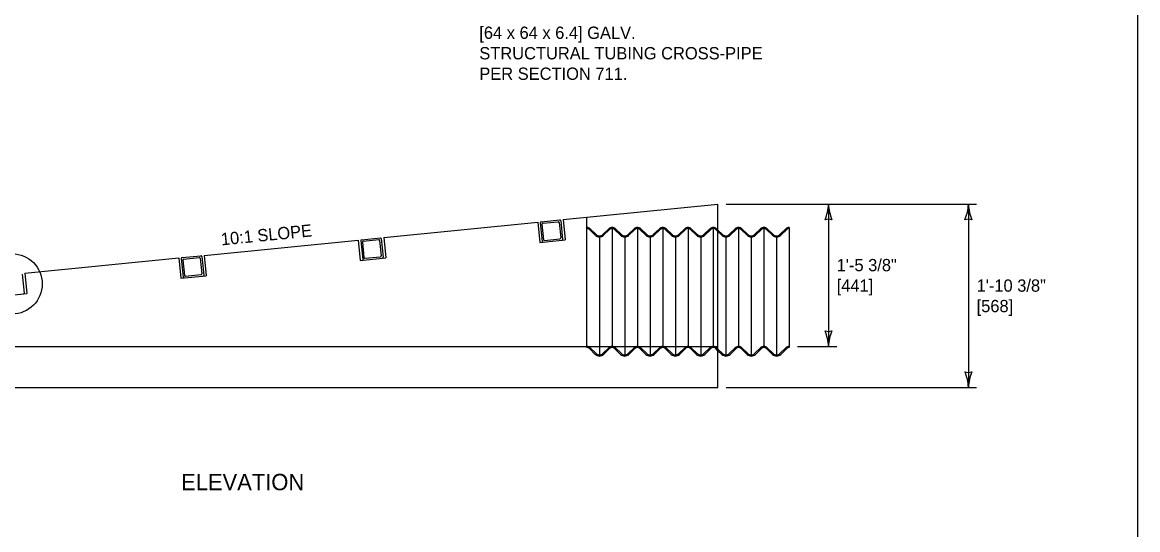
# Model space of a CAD drawing. Extents: x 49991.4 to 50021, y 49987.6 to 50011.4.
# Drawn here: x 50003.17 to 50008.61, y 50005.56 to 50008.04 of the extents above; entities that cross this region are included whole.
import ezdxf

# ---------------------------------------------------------------- set-up
doc = ezdxf.new("R2010")
doc.units = 0
for name, color, linetype in [('Level 1', 7, 'Continuous'), ('Level 2', 7, 'Continuous'), ('Level 3', 7, 'Continuous'), ('Level 4', 7, 'Continuous')]:
    doc.layers.add(name, color=color, linetype=linetype)

msp = doc.modelspace()

# ---------------------------------------------------------------- linework, layer by layer
at = {"layer": 'Level 1'}
for p, q in [((50005.8118, 50007.0772), (50006.5671, 50007.1526)), ((50006.5671, 50006.2576), (50006.5671, 50007.1526)), ((50004.9361, 50006.9899), (50005.6878, 50007.0648)), ((50005.6878, 50007.0648), (50005.6977, 50006.9653)), ((50005.7038, 50007.0664), (50005.7958, 50007.0756)), ((50005.7118, 50007.0592), (50005.7878, 50007.0668)), ((50005.8002, 50007.072), (50005.8093, 50006.9805)), ((50005.8118, 50007.0772), (50005.8217, 50006.9777)), ((50005.7002, 50007.062), (50005.7093, 50006.9705)), ((50005.7082, 50007.0548), (50005.7157, 50006.9792)), ((50005.7922, 50007.0632), (50005.7997, 50006.9876)), ((50006.5898, 50007.0046), (50006.5671, 50007.0262)), ((50006.5859, 50007.0007), (50006.5671, 50007.0185)), ((50006.6516, 50007.0326), (50006.6223, 50007.0046)), ((50006.6554, 50007.0286), (50006.6261, 50007.0007)), ((50006.6678, 50007.0391), (50006.6678, 50006.4521)), ((50006.68, 50007.0286), (50006.7093, 50007.0007)), ((50006.6839, 50007.0326), (50006.7132, 50007.0046)), ((50006.7457, 50007.0046), (50006.775, 50007.0326)), ((50006.7496, 50007.0007), (50006.7789, 50007.0286)), ((50006.7911, 50007.0391), (50006.7911, 50006.4521)), ((50006.8327, 50007.0007), (50006.8035, 50007.0286)), ((50006.8366, 50007.0046), (50006.8073, 50007.0326)), ((50006.8984, 50007.0326), (50006.8691, 50007.0046)), ((50006.9023, 50007.0286), (50006.873, 50007.0007)), ((50006.9146, 50007.0391), (50006.9146, 50006.4521)), ((50004.0605, 50006.9024), (50004.8121, 50006.9775)), ((50004.8121, 50006.9775), (50004.822, 50006.878)), ((50004.8245, 50006.9747), (50004.8337, 50006.8832)), ((50004.8281, 50006.9791), (50004.9202, 50006.9883)), ((50004.8325, 50006.9675), (50004.8401, 50006.8918)), ((50004.8361, 50006.9718), (50004.9122, 50006.9794)), ((50004.9165, 50006.9758), (50004.9241, 50006.9002)), ((50004.9245, 50006.9847), (50004.9336, 50006.8932)), ((50004.9361, 50006.9899), (50004.946, 50006.8904)), ((50005.6977, 50006.9653), (50005.8217, 50006.9777)), ((50005.7201, 50006.9756), (50005.7961, 50006.9832)), ((50006.606, 50006.998), (50006.606, 50006.4109)), ((50006.7294, 50006.998), (50006.7294, 50006.4109)), ((50006.8529, 50006.998), (50006.8529, 50006.4109)), ((50004.0605, 50006.9024), (50004.0704, 50006.803)), ((50003.1848, 50006.8151), (50003.9365, 50006.8901)), ((50003.9365, 50006.8901), (50003.9464, 50006.7906)), ((50003.9489, 50006.8873), (50003.958, 50006.7958)), ((50003.9524, 50006.8917), (50004.0445, 50006.9009)), ((50003.9569, 50006.88), (50003.9644, 50006.8044)), ((50003.9604, 50006.8844), (50004.0365, 50006.892)), ((50004.0409, 50006.8884), (50004.0484, 50006.8128)), ((50004.0489, 50006.8973), (50004.058, 50006.8057)), ((50004.822, 50006.878), (50004.946, 50006.8904)), ((50004.8444, 50006.8883), (50004.9205, 50006.8958)), ((50003.1732, 50006.81), (50003.1823, 50006.7184)), ((50003.1848, 50006.8151), (50003.1947, 50006.7156)), ((50003.9464, 50006.7906), (50004.0704, 50006.803)), ((50003.9688, 50006.8008), (50004.0448, 50006.8084)), ((50003.0707, 50006.7032), (50003.1947, 50006.7156)), ((50006.5898, 50006.4231), (50006.5671, 50006.4446)), ((50006.5859, 50006.4192), (50006.5671, 50006.4369)), ((50006.6516, 50006.451), (50006.6223, 50006.4231)), ((50006.6554, 50006.4471), (50006.6261, 50006.4192)), ((50006.68, 50006.4471), (50006.7093, 50006.4192)), ((50006.6839, 50006.451), (50006.7132, 50006.4231)), ((50006.7457, 50006.4231), (50006.775, 50006.451)), ((50006.7496, 50006.4192), (50006.7789, 50006.4471)), ((50006.8327, 50006.4192), (50006.8035, 50006.4471)), ((50006.8366, 50006.4231), (50006.8073, 50006.451)), ((50006.8984, 50006.451), (50006.8691, 50006.4231)), ((50006.9023, 50006.4471), (50006.873, 50006.4192)), ((50002.0071, 50006.2576), (50006.5671, 50006.2576))]:
    msp.add_line(p, q, dxfattribs=at)
msp.add_lwpolyline([(50008.6146, 50011.2628), (50000.3356, 50011.2628), (50000.3356, 50000.0624), (50008.6146, 50000.0624)], close=True, dxfattribs=at)
for centre, radius, start, end in [((50005.7042, 50007.0624), 0.00402, 95.7106, 185.7106), ((50005.7882, 50007.0628), 0.00402, 5.7106, 95.7106), ((50005.7962, 50007.0716), 0.00402, 5.7106, 95.7106), ((50005.7122, 50007.0552), 0.00402, 95.7106, 185.7106), ((50006.6677, 50007.016), 0.0231, 90, 134.2931), ((50006.6677, 50007.016), 0.0176, 90, 134.2931), ((50006.6677, 50007.016), 0.0231, 45.7069, 90), ((50006.6677, 50007.016), 0.0176, 45.7069, 90), ((50006.7912, 50007.016), 0.0231, 90, 134.2931), ((50006.7912, 50007.016), 0.0176, 90, 134.2931), ((50006.7912, 50007.016), 0.0231, 45.7069, 90), ((50006.7912, 50007.016), 0.0176, 45.7069, 90), ((50006.9146, 50007.016), 0.0231, 89.9558, 134.2931), ((50006.9146, 50007.016), 0.0176, 89.9419, 134.2931), ((50004.8285, 50006.9751), 0.00402, 95.7106, 185.7106), ((50004.8365, 50006.9678), 0.00397, 95.0636, 185.0636), ((50004.9125, 50006.9754), 0.00397, 5.0636, 95.0636), ((50004.9205, 50006.9843), 0.00397, 5.0636, 95.0636), ((50005.7133, 50006.9709), 0.004, 185.4798, 275.4798), ((50005.7197, 50006.9796), 0.00402, 185.7106, 275.7106), ((50005.7957, 50006.9872), 0.00402, 275.7106, 5.7106), ((50005.8053, 50006.9801), 0.00402, 275.7587, 5.7587), ((50006.606, 50007.0211), 0.0287, 225.4064, 270), ((50006.606, 50007.0211), 0.0231, 225.4064, 270), ((50006.606, 50007.0211), 0.0231, 270, 314.5936), ((50006.606, 50007.0211), 0.0287, 270, 314.5936), ((50006.7294, 50007.0211), 0.0287, 225.4064, 270), ((50006.7294, 50007.0211), 0.0231, 225.4064, 270), ((50006.7294, 50007.0211), 0.0231, 270, 314.5936), ((50006.7294, 50007.0211), 0.0287, 270, 314.5936), ((50006.8529, 50007.0211), 0.0287, 225.4064, 270), ((50006.8529, 50007.0211), 0.0231, 225.4064, 270), ((50006.8529, 50007.0211), 0.0231, 270, 314.5936), ((50006.8529, 50007.0211), 0.0287, 270, 314.5936), ((50003.9529, 50006.8877), 0.00398, 96.4993, 186.4993), ((50003.9609, 50006.8805), 0.00398, 96.4993, 186.4993), ((50004.0369, 50006.888), 0.00402, 5.7106, 95.7106), ((50004.0449, 50006.8969), 0.00402, 5.7106, 95.7106), ((50004.8374, 50006.8832), 0.0037, 180.632, 270.632), ((50004.844, 50006.8922), 0.00392, 185.856, 275.856), ((50004.9201, 50006.8998), 0.00402, 275.7106, 5.7106), ((50004.93, 50006.8925), 0.00367, 281.4998, 11.4998), ((50003.962, 50006.7962), 0.00401, 185.3804, 275.3804), ((50003.9684, 50006.8048), 0.00402, 185.7106, 275.7106), ((50004.0444, 50006.8124), 0.00402, 275.7106, 5.7106), ((50004.0543, 50006.8051), 0.00374, 278.6164, 8.6164), ((50003.1783, 50006.718), 0.004, 276.1111, 6.1111), ((50006.606, 50006.4396), 0.0287, 225.4064, 270), ((50006.606, 50006.4396), 0.0231, 225.4064, 270), ((50006.606, 50006.4396), 0.0231, 270, 314.5936), ((50006.606, 50006.4396), 0.0287, 270, 314.5936), ((50006.6677, 50006.4345), 0.0231, 90, 134.2931), ((50006.6677, 50006.4345), 0.0176, 90, 134.2931), ((50006.6677, 50006.4345), 0.0231, 45.7069, 90), ((50006.6677, 50006.4345), 0.0176, 45.7069, 90), ((50006.7294, 50006.4396), 0.0287, 225.4064, 270), ((50006.7294, 50006.4396), 0.0231, 225.4064, 270), ((50006.7294, 50006.4396), 0.0231, 270, 314.5936), ((50006.7294, 50006.4396), 0.0287, 270, 314.5936), ((50006.7912, 50006.4345), 0.0231, 90, 134.2931), ((50006.7912, 50006.4345), 0.0176, 90, 134.2931), ((50006.7912, 50006.4345), 0.0231, 45.7069, 90), ((50006.7912, 50006.4345), 0.0176, 45.7069, 90), ((50006.8529, 50006.4396), 0.0287, 225.4064, 270), ((50006.8529, 50006.4396), 0.0231, 225.4064, 270), ((50006.8529, 50006.4396), 0.0231, 270, 314.5936), ((50006.8529, 50006.4396), 0.0287, 270, 314.5936), ((50006.9146, 50006.4345), 0.0231, 89.9558, 134.2931), ((50006.9146, 50006.4345), 0.0176, 89.9419, 134.2931)]:
    msp.add_arc(centre, radius, start, end, dxfattribs=at)
at = {"layer": 'Level 3'}
for p, q in [((50006.6071, 50007.1526), (50007.8287, 50007.1526)), ((50007.1061, 50007.1526), (50007.1061, 50006.4576)), ((50007.7887, 50007.1526), (50007.7887, 50006.2576)), ((50006.9546, 50006.4576), (50007.1461, 50006.4576)), ((50006.6071, 50006.2576), (50007.8287, 50006.2576))]:
    msp.add_line(p, q, dxfattribs=at)
msp.add_circle((50003.1234, 50006.7633), 0.1472, dxfattribs=at)
for centre, radius, start, end in [((50006.884, 50007.1618), 0.2223, 337.456, 357.6395), ((50007.3388, 50007.1641), 0.233, 182.8273, 202.0772), ((50007.5665, 50007.1618), 0.2223, 337.456, 357.6395), ((50008.0214, 50007.1641), 0.233, 182.8273, 202.0772), ((50007.1061, 50007.0244), 0.0548, 72.1388, 107.8612), ((50007.7887, 50007.0244), 0.0548, 72.1388, 107.8612), ((50007.1061, 50006.5858), 0.0548, 252.1388, 287.8612), ((50006.8734, 50006.4461), 0.233, 2.8273, 22.0772), ((50007.3282, 50006.4484), 0.2223, 157.456, 177.6395), ((50007.7887, 50006.3858), 0.0548, 252.1388, 287.8612), ((50007.556, 50006.2461), 0.233, 2.8273, 22.0772), ((50008.0108, 50006.2484), 0.2223, 157.456, 177.6395)]:
    msp.add_arc(centre, radius, start, end, dxfattribs=at)
at = {"layer": 'Level 4'}
for p, q in [((50005.9271, 50006.4521), (50005.9271, 50007.0887)), ((50005.9395, 50007.0286), (50005.9687, 50007.0007)), ((50005.9433, 50007.0326), (50005.9726, 50007.0046)), ((50006.0051, 50007.0046), (50006.0344, 50007.0326)), ((50006.009, 50007.0007), (50006.0383, 50007.0286)), ((50006.0506, 50007.0391), (50006.0506, 50006.4521)), ((50006.0922, 50007.0007), (50006.0629, 50007.0286)), ((50006.096, 50007.0046), (50006.0667, 50007.0326)), ((50006.1578, 50007.0326), (50006.1285, 50007.0046)), ((50006.1617, 50007.0286), (50006.1324, 50007.0007)), ((50006.174, 50007.0391), (50006.174, 50006.4521)), ((50006.1863, 50007.0286), (50006.2156, 50007.0007)), ((50006.1902, 50007.0326), (50006.2195, 50007.0046)), ((50006.2515, 50007.0042), (50006.2813, 50007.0326)), ((50006.2559, 50007.0007), (50006.2851, 50007.0286)), ((50006.2974, 50007.0391), (50006.2974, 50006.4521)), ((50006.339, 50007.0007), (50006.3097, 50007.0286)), ((50006.3429, 50007.0046), (50006.3136, 50007.0326)), ((50006.4047, 50007.0326), (50006.3754, 50007.0046)), ((50006.4086, 50007.0286), (50006.3793, 50007.0007)), ((50006.4209, 50007.0391), (50006.4209, 50006.4521)), ((50006.4332, 50007.0286), (50006.4624, 50007.0007)), ((50006.437, 50007.0326), (50006.4663, 50007.0046)), ((50006.4988, 50007.0046), (50006.5281, 50007.0326)), ((50006.5027, 50007.0007), (50006.532, 50007.0286)), ((50006.5443, 50007.0391), (50006.5443, 50006.4521)), ((50006.5671, 50007.0185), (50006.5566, 50007.0286)), ((50006.5671, 50007.0262), (50006.5605, 50007.0326)), ((50005.9889, 50006.998), (50005.9889, 50006.4109)), ((50006.1123, 50006.998), (50006.1123, 50006.4109)), ((50006.2358, 50006.998), (50006.2358, 50006.4109)), ((50006.3591, 50006.998), (50006.3591, 50006.4109)), ((50006.4826, 50006.998), (50006.4826, 50006.4109)), ((50002.0071, 50006.4576), (50006.5671, 50006.4576)), ((50005.9395, 50006.4471), (50005.9687, 50006.4192)), ((50005.9433, 50006.451), (50005.9726, 50006.4231)), ((50006.0051, 50006.4231), (50006.0344, 50006.451)), ((50006.009, 50006.4192), (50006.0383, 50006.4471)), ((50006.0922, 50006.4192), (50006.0629, 50006.4471)), ((50006.096, 50006.4231), (50006.0667, 50006.451)), ((50006.1578, 50006.451), (50006.1285, 50006.4231)), ((50006.1617, 50006.4471), (50006.1324, 50006.4192)), ((50006.1863, 50006.4471), (50006.2156, 50006.4192)), ((50006.1902, 50006.451), (50006.2195, 50006.4231)), ((50006.252, 50006.4231), (50006.2813, 50006.451)), ((50006.2559, 50006.4192), (50006.2851, 50006.4471)), ((50006.339, 50006.4192), (50006.3097, 50006.4471)), ((50006.3429, 50006.4231), (50006.3136, 50006.451)), ((50006.4047, 50006.451), (50006.3754, 50006.4231)), ((50006.4086, 50006.4471), (50006.3793, 50006.4192)), ((50006.4332, 50006.4471), (50006.4624, 50006.4192)), ((50006.437, 50006.451), (50006.4663, 50006.4231)), ((50006.4988, 50006.4231), (50006.5281, 50006.451)), ((50006.5027, 50006.4192), (50006.532, 50006.4471)), ((50006.5671, 50006.4369), (50006.5566, 50006.4471)), ((50006.5671, 50006.4446), (50006.5605, 50006.451))]:
    msp.add_line(p, q, dxfattribs=at)
for centre, radius, start, end in [((50005.9272, 50007.016), 0.0231, 45.7069, 90.1313), ((50005.9272, 50007.016), 0.0176, 45.7069, 90.1725), ((50006.0506, 50007.016), 0.0231, 90, 134.2931), ((50006.0506, 50007.016), 0.0176, 90, 134.2931), ((50006.0506, 50007.016), 0.0231, 45.7069, 90), ((50006.0506, 50007.016), 0.0176, 45.7069, 90), ((50006.174, 50007.016), 0.0231, 90, 134.2931), ((50006.174, 50007.016), 0.0176, 90, 134.2931), ((50006.174, 50007.016), 0.0231, 45.7069, 90), ((50006.174, 50007.016), 0.0176, 45.7069, 90), ((50006.2974, 50007.016), 0.0231, 90, 134.2931), ((50006.2974, 50007.016), 0.0176, 90, 134.2931), ((50006.2974, 50007.016), 0.0231, 45.7069, 90), ((50006.2974, 50007.016), 0.0176, 45.7069, 90), ((50006.4209, 50007.016), 0.0231, 90, 134.2931), ((50006.4209, 50007.016), 0.0176, 90, 134.2931), ((50006.4209, 50007.016), 0.0231, 45.7069, 90), ((50006.4209, 50007.016), 0.0176, 45.7069, 90), ((50006.5443, 50007.016), 0.0231, 90, 134.2931), ((50006.5443, 50007.016), 0.0176, 90, 134.2931), ((50006.5443, 50007.016), 0.0231, 45.7069, 90), ((50006.5443, 50007.016), 0.0176, 45.7069, 90), ((50005.9889, 50007.0211), 0.0287, 225.4064, 270), ((50005.9889, 50007.0211), 0.0231, 225.4064, 270), ((50005.9889, 50007.0211), 0.0231, 270, 314.5936), ((50005.9889, 50007.0211), 0.0287, 270, 314.5936), ((50006.1123, 50007.0211), 0.0287, 225.4064, 270), ((50006.1123, 50007.0211), 0.0231, 225.4064, 270), ((50006.1123, 50007.0211), 0.0231, 270, 314.5936), ((50006.1123, 50007.0211), 0.0287, 270, 314.5936), ((50006.2357, 50007.0211), 0.0287, 225.4064, 270), ((50006.2357, 50007.0211), 0.0231, 225.4064, 270), ((50006.2357, 50007.0211), 0.0231, 270, 314.5936), ((50006.2357, 50007.0211), 0.0287, 270, 314.5936), ((50006.3592, 50007.0211), 0.0287, 225.4064, 270), ((50006.3592, 50007.0211), 0.0231, 225.4064, 270), ((50006.3592, 50007.0211), 0.0231, 270, 314.5936), ((50006.3592, 50007.0211), 0.0287, 270, 314.5936), ((50006.4826, 50007.0211), 0.0287, 225.4064, 270), ((50006.4826, 50007.0211), 0.0231, 225.4064, 270), ((50006.4826, 50007.0211), 0.0231, 270, 314.5936), ((50006.4826, 50007.0211), 0.0287, 270, 314.5936), ((50005.9272, 50006.4345), 0.0231, 45.7069, 90.1313), ((50005.9272, 50006.4345), 0.0176, 45.7069, 90.1725), ((50005.9889, 50006.4396), 0.0287, 225.4064, 270), ((50005.9889, 50006.4396), 0.0231, 225.4064, 270), ((50005.9889, 50006.4396), 0.0231, 270, 314.5936), ((50005.9889, 50006.4396), 0.0287, 270, 314.5936), ((50006.0506, 50006.4345), 0.0231, 90, 134.2931), ((50006.0506, 50006.4345), 0.0176, 90, 134.2931), ((50006.0506, 50006.4345), 0.0231, 45.7069, 90), ((50006.0506, 50006.4345), 0.0176, 45.7069, 90), ((50006.1123, 50006.4396), 0.0287, 225.4064, 270), ((50006.1123, 50006.4396), 0.0231, 225.4064, 270), ((50006.1123, 50006.4396), 0.0231, 270, 314.5936), ((50006.1123, 50006.4396), 0.0287, 270, 314.5936), ((50006.174, 50006.4345), 0.0231, 90, 134.2931), ((50006.174, 50006.4345), 0.0176, 90, 134.2931), ((50006.174, 50006.4345), 0.0231, 45.7069, 90), ((50006.174, 50006.4345), 0.0176, 45.7069, 90), ((50006.2357, 50006.4396), 0.0287, 225.4064, 270), ((50006.2357, 50006.4396), 0.0231, 225.4064, 270), ((50006.2357, 50006.4396), 0.0231, 270, 314.5936), ((50006.2357, 50006.4396), 0.0287, 270, 314.5936), ((50006.2974, 50006.4345), 0.0231, 90, 134.2931), ((50006.2974, 50006.4345), 0.0176, 90, 134.2931), ((50006.2974, 50006.4345), 0.0231, 45.7069, 90), ((50006.2974, 50006.4345), 0.0176, 45.7069, 90), ((50006.3592, 50006.4396), 0.0287, 225.4064, 270), ((50006.3592, 50006.4396), 0.0231, 225.4064, 270), ((50006.3592, 50006.4396), 0.0231, 270, 314.5936), ((50006.3592, 50006.4396), 0.0287, 270, 314.5936), ((50006.4209, 50006.4345), 0.0231, 90, 134.2931), ((50006.4209, 50006.4345), 0.0176, 90, 134.2931), ((50006.4209, 50006.4345), 0.0231, 45.7069, 90), ((50006.4209, 50006.4345), 0.0176, 45.7069, 90), ((50006.4826, 50006.4396), 0.0287, 225.4064, 270), ((50006.4826, 50006.4396), 0.0231, 225.4064, 270), ((50006.4826, 50006.4396), 0.0231, 270, 314.5936), ((50006.4826, 50006.4396), 0.0287, 270, 314.5936), ((50006.5443, 50006.4345), 0.0231, 90, 134.2931), ((50006.5443, 50006.4345), 0.0176, 90, 134.2931), ((50006.5443, 50006.4345), 0.0231, 45.7069, 90), ((50006.5443, 50006.4345), 0.0176, 45.7069, 90)]:
    msp.add_arc(centre, radius, start, end, dxfattribs=at)

# ---------------------------------------------------------------- texts
at = {"layer": 'Level 2'}
for s, height, p in [('[64 x 64 x 6.4] GALV.', 0.06, (50005.4027, 50007.9599)), ('STRUCTURAL TUBING CROSS-PIPE', 0.06, (50005.4027, 50007.8599)), ('PER SECTION 711.', 0.06, (50005.4027, 50007.7599)), ('1\'-5 3/8"', 0.06, (50007.1461, 50006.8251)), ('[441]', 0.06, (50007.1461, 50006.7251)), ('1\'-10 3/8"', 0.06, (50007.8287, 50006.7251)), ('[568]', 0.06, (50007.8287, 50006.6251)), ('ELEVATION', 0.08, (50003.948, 50005.7555))]:
    msp.add_text(s, height=height, dxfattribs=at).set_placement(p)
msp.add_text('10:1 SLOPE', height=0.06, rotation=5.7061, dxfattribs=at).set_placement((50004.1453, 50006.9511))

doc.saveas('drawing.dxf')
